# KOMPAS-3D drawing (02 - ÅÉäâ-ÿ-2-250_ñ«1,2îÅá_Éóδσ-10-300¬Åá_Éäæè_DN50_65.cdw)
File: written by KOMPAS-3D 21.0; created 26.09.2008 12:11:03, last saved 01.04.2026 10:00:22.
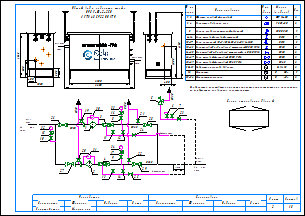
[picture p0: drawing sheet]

Sheets 1-2: A3, landscape

Document properties: Наименование: Макро:21; Автор: RaskoAdmin; Форматы листов документа: 2xA3; Полное имя файла: \\UR38nt01\Departments\КТО\КБ ПУРДГ\Заявки\Прайс-лист на типовые шкафы ГРПШ\ПРДГ_стандарт_20_03_2026\ПРДГ с РДСК\ПРДГ-Ш-2-250_до1,2МПа_Рвых-10-300кПа_РДСК_DN50_65.cdw

Title block, sheet 1: Наименование: Пункт учета газа / ПУГ-Ш-400-Р / ЛГТИ.485922.001ТУ; designation: ЛГТИ.03.4411141; sheet number: 1; Количество листов документа: 2; organisation: ООО "ЭЛЬСТЕР Газэлектроника"; Форматы листов документа: A3; stored path: C:\Рабочие документы\Компас\ПУГ\Схема.cdw; Разработал: Устинов; Проверил: Кошкин; Утвердил: Кошкин
Title block, sheet 2: sheet number: 2; stored path: D:\Рабочие документы\Заявки\ПУРДГ\ПУРДГ-ШУЭО-2-100-Р 4411220.cdw; designation, second copy: ЛГТИ.03.4411141-

Views: Вид 1, Вид 2
Referenced files: wcvoit.frw
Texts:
  Normal
  Вход
  газа
  PDI
  Выход
  Р=     кПа
  DN65
  DN50
  DN20
  Импульс DN20
  ≥5DN
  HYSWLongFangSong
  № на
  схеме
  Усл.
  обозн.
  Марка
  (модель)
  Кол.
  Фильтр газовый фланцевый
  ФГ 16-50
  Регулятор давления газа
  РДCК-50
  Клапан предохранительный сбросной
  КПС DN20
  Кран шаровой газовый латунный
  DN15
  Кран кнопочный VE-РАСКО-НЗ-1,6-G1/2-М20
  Кран шаровой "под приварку" штуцерный DN20 PN16
  Кран шаровой "под приварку" штуцерный п/п DN20 PN16
  Кран шаровой фланцевый DN50 PN16
  Кран шаровой фланцевый DN65 PN16
  Индикатор перепада давления
  Delta 15
  Манометр
  Манометр-напоромер
  0...     МПа
  0...     кПа
  Общий вид и габариты шкафа
  ПРДГ-Ш-2-250
  Выход газа
  Вход газа
  Схема открывания дверей
  Р=        МПа
  logo-rasko-ge.png
  Предприятие изготовитель может заменять комплектующие на аналогичные,
  не ухудшающие заявленных характеристик.
  Должность
  Конструктор
  Фамилия
  Подпись
  Дата
  Согласовано
  Максимкин
  Лист
  Листов
  POLYLINE_STYLE_0.18_RGB_0_0_0
  POLYLINE_STYLE_0.50_RGB_0_0_0
  POLYLINE_STYLE_0.34_RGB_0_0_0
  PHANTOM_RGB_0_0_0_SC_1_THICK_0.18
  K5LT_THIN_RGB_0_0_0_THICK_0.18
  K5LT32769_RGB_0_0_0_THICK_0.18
  K5LT12_RGB_0_0_0_SC_1_THICK_0.18
  K5LT_DASHED_RGB_0_0_0_SC_1_THICK_0.18
  ACISOTGL_RGB_0_0_0_SC_0.8_THICK_0.25
  CONTINUOUS_RGB_0_127_31_THICK_0.3
  CONTINUOUS_RGB_0_0_255_THICK_0.35
  CONTINUOUS_RGB_255_0_0_THICK_0.35
  POLYLINE_STYLE_0.25_RGB_0_0_0
  CONTINUOUS_RGB_0_0_0_THICK_0.5
  POLYLINE_STYLE_0.35_RGB_0_0_255
  CONTINUOUS_RGB_0_0_0_THICK_0.4
  CONTINUOUS_RGB_0_0_0_THICK_0.35
  Без оформления
Dimensions and other numbers on the sheet: 1; 2; 3; 4; 5; 10; 27; 28; 29; 23; 8; 12; 19; 20; 21; 22; 25; 24; 30; 31; 15; 16; 26; 6; 7; 11; 14; 13; 33; 1, 2; 3, 4; 6-14; 9; 15-17; 18-23; 24-25; 26-27; 28-29; 30-31; 32; 33-34; 400; 1050; 500; 305; 2300; 1565; 2600; 17; 34; 1000; 4130; 18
